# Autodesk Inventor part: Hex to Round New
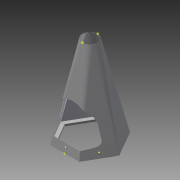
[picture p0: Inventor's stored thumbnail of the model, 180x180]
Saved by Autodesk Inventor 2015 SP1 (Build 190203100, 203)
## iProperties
Created: 2013-06
Part Number: Hex to Round New
Material: Steel, Mild
Document SubType Name: Sheet Metal
Designer: 1103005
Density: 1 g/cm^3
Flat Pattern Width: 84.2512 cm
Flat Pattern Length: 101.013 cm
Flat Pattern Area: 8510.43 cm^2
Sheet Metal Rule: Default_mm
Sheet Metal Width: 842.512 mm
Sheet Metal Length: 1010.126 mm
Sheet Metal Area: 851043.478 mm^2
Appearance: Steel
Author: 1103005
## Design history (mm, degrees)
sketch "Sketch1"
  geometry: L1 (-286.366, 0)-(286.366, 0); L2 (286.366, 0)-(143.183, -248); L3 (143.183, -248)-(-143.183, -248); L4 (-143.183, -248)-(-286.366, 0); L5 (-143.183, -248)-(-286.366, 0); L6 (-286.366, 0)-(-143.183, 248); L7 (-143.183, 248)-(143.183, 248); L8 (143.183, 248)-(286.366, 0); L9 (286.366, 0)-(143.183, -248); L10 (143.183, -248)-(-143.183, -248); 6 further points
  constraints: 20 end point, 4 coincident, 2 midpoint, 1 horizontal, 1 vertical alignment, 19 other
  dimensions: "d26" = 248 distance between parallel lines of L1 L3
workplane "Work Plane1"
node "Lofted Flange1"
  sketch "Sketch2"
    geometry: L1 (74, 0)-(-74, 0); A1 r 74 centre (0, 0) between (-74, 0) and (74, 0); 1 further point
    constraints: 2 end point, 2 point on circle, 1 centre point, 1 coincident, 1 horizontal, 1 midpoint
    dimensions: "d2" = 148 diameter of A1
workpoint "Work Point1"
workpoint "Work Point2"
feature "Rip1" dims "d40" = 0.5
workpoint "Work Point3"
workpoint "Work Point4"
mirror "Mirror1"
cut "Cut2" dims "d76" = 1.2 (derived), "d77" = 0
sketch "Sketch19"
  geometry: 1 further point
sketch "Sketch20"
  geometry: 1 further point
sketch "Sketch22"
  geometry: 1 further point
cut "Cut3" dims "d88" = 1.2 (derived), "d89" = 0
node "Flange3"
node "Flange4"
node "Flange5"
node "Flange6"
node "Flange7"
node "Flange8"
node "Flange9"
node "Flange10"
sketch "Sketch31"
  geometry: 1 further point
sketch "Sketch32"
  geometry: 1 further point
sketch "Sketch33"
  geometry: 1 further point
sketch "Sketch34"
  geometry: 1 further point
body "Solid1"
sketch "Sketch21"
  geometry: L1 (0, 0)-(0, 80); L2 (0, 80)-(135, 80); L3 (0, 80)-(0, 230); L4 (0, 866.106)-(0, 0) reference; L5 (135, 80)-(178.687, 101.843); L6 (135, 80)-(183.843, 80); L7 (204.686, 159.267)-(174.094, 275.73); A1 r 180 centre (0, 230) between (174.094, 275.73) and (0, 410); A2 r 50 centre (156.326, 146.565) between (178.687, 101.843) and (204.686, 159.267); 4 further points
  constraints: 12 end point, 6 point on line, 4 point on circle, 3 tangent, 2 centre point, 1 coincident, 1 equal length, 1 horizontal, 1 perpendicular, 1 vertical
  dimensions: "d81" = 80 distance of L1.start L1.end; "d82" = 135 distance of L1.end L2.end; "d83" = 150 distance of L1.end L3.end; "d84" = 360 diameter of A1; "d86" = 40 vertical distance of L2.end point (215, 120); "d87" = 80 horizontal distance of L2.end point (215, 120); "d176" = 50 radius of A2
bend "Bend1" dims "d4" = 1.2 (= BendRadius), "d5" = 1.2 (= BendReliefWidth), "d6" = 0.6 (= BendReliefDepth), "d7" = 2.4 (= MinimumRemnant), "d8" = 1.2 (= BendRadius), "SeamGap" = 0.01, "Thickness" = 1.2
sketch "Sketch13"
  geometry: L1 (142.752, 0)-(142.752, 80); L2 (142.752, 0)-(142.752, 866.106) reference; L3 (142.752, 80)-(142.752, 230); L4 (142.752, 895.908)-(142.752, 99.474) reference; L5 (7.252, 80)-(-36.323, 101.788); L6 (142.252, 0)-(142.252, 866.105) reference; L7 (142.252, 866.105)-(0, 0) reference; L8 (0, 0)-(142.252, 0) reference; L9 (-62.284, 159.357)-(-31.204, 276.251); L10 (7.252, 80)-(142.252, 80); A1 r 176.137 centre (142.752, 230) between (142.252, 53.863) and (142.752, 53.863); A2 r 180 centre (142.752, 230) between (142.752, 410) and (-31.204, 276.251); A3 r 180 centre (142.752, 230) between (142.252, 50.001) and (142.752, 50); A4 r 50 centre (-13.962, 146.509) between (-62.284, 159.357) and (-36.323, 101.788); 4 further points
  constraints: 12 point on line, 10 end point, 8 point on circle, 4 centre point, 3 tangent, 2 coincident, 1 horizontal
  dimensions: "d66" = 80 distance of L1.start L1.end; "d68" = 150 distance of L1.end L3.end; "d70" = 80 horizontal distance of point (-72.748, 120) L5.start; "d75" = 40 vertical distance of L5.start point (-72.748, 120); "d172" = 135 distance of L5.start L10.end; "d174" = 180 radius of A2; "d175" = 50 radius of A4
node "Projected Loop2"
sketch "Sketch23"
  geometry: L1 through (-71.249, 123.412) direction (0.5, -0.866); L2 through (15.156, 8.75) direction (0.866, 0.5); L3 (30.311, 17.499)-(-112.187, 264.323); L4 (-112.187, 264.323)-(-142.498, 246.824)
  constraints: 6 end point, 1 perpendicular, 2 other
face "Plate3" dims "d90" = 1.2 (derived), "d91" = 0.6 (derived), "d92" = 2.4 (derived), "d93" = 1.2 (derived), "d94" = 35, "d95" = 17.63655, "d96" = 1.2 (derived), "d97" = 4.8 (derived), "d98" = 1.2 (derived), "d99" = 1.2 (derived), "SeamGap" = 0.01, "Thickness" = 1.2
bend "Bend4" dims "d90" = 1.2 (derived), "d91" = 0.6 (derived), "d92" = 2.4 (derived), "d93" = 1.2 (derived), "d94" = 35, "d95" = 17.63655, "d96" = 1.2 (derived), "SeamGap" = 0.01, "Thickness" = 1.2
feature "Corner3" dims "d94" = 35, "d95" = 17.63655, "d97" = 4.8 (derived), "d98" = 1.2 (derived), "d99" = 1.2 (derived)
sketch "Sketch24"
  geometry: L1 through (61.353, 0) direction (-1, 2.94e-16); L2 through (0, -12.5) direction (-7.28e-16, -1); L3 (0, -25)-(122.706, -25); L4 (122.706, -25)-(122.706, 0)
  constraints: 6 end point, 1 horizontal, 1 perpendicular, 1 vertical
face "Plate4" dims "d100" = 1.2 (derived), "d101" = 0.6 (derived), "d102" = 2.4 (derived), "d103" = 1.2 (derived), "d104" = 25, "d105" = 90 deg, "d106" = 1.2 (derived), "d107" = 4.8 (derived), "d108" = 1.2 (derived), "d109" = 1.2 (derived), "SeamGap" = 0.01, "Thickness" = 1.2
bend "Bend5" dims "d100" = 1.2 (derived), "d101" = 0.6 (derived), "d102" = 2.4 (derived), "d103" = 1.2 (derived), "d104" = 25, "d105" = 90 deg, "d106" = 1.2 (derived), "SeamGap" = 0.01, "Thickness" = 1.2
feature "Corner4" dims "d104" = 25, "d105" = 90 deg, "d107" = 4.8 (derived), "d108" = 1.2 (derived), "d109" = 1.2 (derived)
sketch "Sketch25"
  geometry: L1 through (122.956, 0) direction (-1, 1.3e-15); L2 through (0, -12.5) direction (-5.9e-16, -1); L3 (0, -25)-(245.912, -25); L4 (245.912, -25)-(245.912, 0)
  constraints: 6 end point, 1 horizontal, 1 perpendicular, 1 vertical
face "Plate5" dims "d110" = 1.2 (derived), "d111" = 0.6 (derived), "d112" = 2.4 (derived), "d113" = 1.2 (derived), "d114" = 25, "d115" = 90 deg, "d116" = 1.2 (derived), "d117" = 4.8 (derived), "d118" = 1.2 (derived), "d119" = 1.2 (derived), "SeamGap" = 0.01, "Thickness" = 1.2
bend "Bend6" dims "d110" = 1.2 (derived), "d111" = 0.6 (derived), "d112" = 2.4 (derived), "d113" = 1.2 (derived), "d114" = 25, "d115" = 90 deg, "d116" = 1.2 (derived), "SeamGap" = 0.01, "Thickness" = 1.2
feature "Corner5" dims "d114" = 25, "d115" = 90 deg, "d117" = 4.8 (derived), "d118" = 1.2 (derived), "d119" = 1.2 (derived)
sketch "Sketch26"
  geometry: L1 through (61.353, 0) direction (-1, -5.84e-16); L2 through (0, -12.5) direction (1.29e-15, -1); L3 (0, -25)-(122.706, -25); L4 (122.706, -25)-(122.706, 0)
  constraints: 6 end point, 1 horizontal, 1 perpendicular, 1 vertical
face "Plate6" dims "d120" = 1.2 (derived), "d121" = 0.6 (derived), "d122" = 2.4 (derived), "d123" = 1.2 (derived), "d124" = 25, "d125" = 90 deg, "d126" = 1.2 (derived), "d127" = 4.8 (derived), "d128" = 1.2 (derived), "d129" = 1.2 (derived), "SeamGap" = 0.01, "Thickness" = 1.2
bend "Bend7" dims "d120" = 1.2 (derived), "d121" = 0.6 (derived), "d122" = 2.4 (derived), "d123" = 1.2 (derived), "d124" = 25, "d125" = 90 deg, "d126" = 1.2 (derived), "SeamGap" = 0.01, "Thickness" = 1.2
feature "Corner6" dims "d124" = 25, "d125" = 90 deg, "d127" = 4.8 (derived), "d128" = 1.2 (derived), "d129" = 1.2 (derived)
sketch "Sketch27"
  geometry: L1 (122.706, 0)-(0, 0); L2 (0, 0)-(0, -25); L3 (0, -25)-(122.706, -25); L4 (122.706, -25)-(122.706, 0)
  constraints: 8 end point
face "Plate7" dims "d130" = 1.2 (derived), "d131" = 0.6 (derived), "d132" = 2.4 (derived), "d133" = 1.2 (derived), "d134" = 25, "d135" = 90 deg, "d136" = 1.2 (derived), "d137" = 4.8 (derived), "d138" = 1.2 (derived), "d139" = 1.2 (derived), "SeamGap" = 0.01, "Thickness" = 1.2
bend "Bend8" dims "d130" = 1.2 (derived), "d131" = 0.6 (derived), "d132" = 2.4 (derived), "d133" = 1.2 (derived), "d134" = 25, "d135" = 90 deg, "d136" = 1.2 (derived), "SeamGap" = 0.01, "Thickness" = 1.2
feature "Corner7" dims "d134" = 25, "d135" = 90 deg, "d137" = 4.8 (derived), "d138" = 1.2 (derived), "d139" = 1.2 (derived)
sketch "Sketch28"
  geometry: L1 through (122.956, 0) direction (-1, 8.71e-16); L2 through (0, -10) direction (-1.95e-15, -1); L3 (0, -20)-(245.912, -20); L4 (245.912, -20)-(245.912, 0)
  constraints: 6 end point, 1 horizontal, 1 perpendicular, 1 vertical
face "Plate8" dims "d140" = 1.2 (derived), "d141" = 0.6 (derived), "d142" = 2.4 (derived), "d143" = 1.2 (derived), "d144" = 20, "d145" = 90 deg, "d146" = 1.2 (derived), "d147" = 4.8 (derived), "d148" = 1.2 (derived), "d149" = 1.2 (derived), "SeamGap" = 0.01, "Thickness" = 1.2
bend "Bend9" dims "d140" = 1.2 (derived), "d141" = 0.6 (derived), "d142" = 2.4 (derived), "d143" = 1.2 (derived), "d144" = 20, "d145" = 90 deg, "d146" = 1.2 (derived), "SeamGap" = 0.01, "Thickness" = 1.2
feature "Corner8" dims "d144" = 20, "d145" = 90 deg, "d147" = 4.8 (derived), "d148" = 1.2 (derived), "d149" = 1.2 (derived)
sketch "Sketch29"
  geometry: L1 through (122.956, 0) direction (-1, 1.16e-15); L2 through (0, -12.5) direction (-1.11e-15, -1); L3 (0, -25)-(245.912, -25); L4 (245.912, -25)-(245.912, 0)
  constraints: 6 end point, 1 horizontal, 1 perpendicular, 1 vertical
face "Plate9" dims "d150" = 1.2 (derived), "d151" = 0.6 (derived), "d152" = 2.4 (derived), "d153" = 1.2 (derived), "d154" = 25, "d155" = 90 deg, "d156" = 1.2 (derived), "d157" = 4.8 (derived), "d158" = 1.2 (derived), "d159" = 1.2 (derived), "SeamGap" = 0.01, "Thickness" = 1.2
bend "Bend10" dims "d150" = 1.2 (derived), "d151" = 0.6 (derived), "d152" = 2.4 (derived), "d153" = 1.2 (derived), "d154" = 25, "d155" = 90 deg, "d156" = 1.2 (derived), "SeamGap" = 0.01, "Thickness" = 1.2
feature "Corner9" dims "d154" = 25, "d155" = 90 deg, "d157" = 4.8 (derived), "d158" = 1.2 (derived), "d159" = 1.2 (derived)
sketch "Sketch30"
  geometry: L1 through (61.353, 0) direction (-1, 2.9e-16); L2 through (0, -12.5) direction (-5.54e-16, -1); L3 (0, -25)-(122.706, -25); L4 (122.706, -25)-(122.706, 0)
  constraints: 6 end point, 1 horizontal, 1 perpendicular, 1 vertical
face "Plate10" dims "d160" = 1.2 (derived), "d161" = 0.6 (derived), "d162" = 2.4 (derived), "d163" = 1.2 (derived), "d164" = 25, "d165" = 90 deg, "d166" = 1.2 (derived), "d167" = 4.8 (derived), "d168" = 1.2 (derived), "d169" = 1.2 (derived), "SeamGap" = 0.01, "Thickness" = 1.2
bend "Bend11" dims "d160" = 1.2 (derived), "d161" = 0.6 (derived), "d162" = 2.4 (derived), "d163" = 1.2 (derived), "d164" = 25, "d165" = 90 deg, "d166" = 1.2 (derived), "SeamGap" = 0.01, "Thickness" = 1.2
feature "Corner10" dims "d164" = 25, "d165" = 90 deg, "d167" = 4.8 (derived), "d168" = 1.2 (derived), "d169" = 1.2 (derived)
feature "Definition1"
other parameters: "BendRadius" = 1.2 (= Thickness), "BendReliefWidth" = 1.2 (= Thickness), "BendReliefDepth" = 0.6 (= 0.5 x Thickness), "CornerReliefSize" = 4.8 (= 4 x Thickness), "MinimumRemnant" = 2.4 (= 2 x Thickness), "TransitionRadius" = 1.2 (= BendRadius), "JacobiRadiusSize" = 1.2 (= BendRadius), "GapSize" = 1.2 (= Thickness), "d3" = 0.5, "d54" = 5 deg, "BendRadius" = 1.2, "BendReliefDepth" = 0.6, "BendReliefWidth" = 1.2, "CornerReliefSize" = 4.8, "GapSize" = 1.2, "JacobiRadiusSize" = 1.2, "MinimumRemnant" = 2.4, "Thickness" = 1.2, "TransitionRadius" = 1.2
